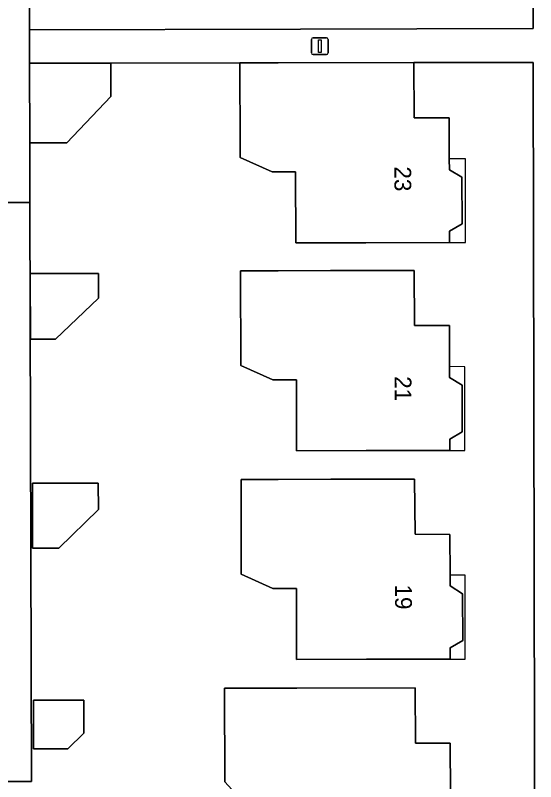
# Model space of a CAD drawing. Extents: x 160455 to 162082, y 388339 to 389736.
# Drawn here: x 160984.32 to 161015.38, y 388503.52 to 388549.23 of the extents above; entities that cross this region are included whole.
import ezdxf

# ---------------------------------------------------------------- set-up
doc = ezdxf.new("R2010")
doc.units = 0
for name, color, linetype in [('IMGEO_Erf', 7, 'Continuous'), ('IMGEO_Lichtmast', 7, 'Continuous'), ('IMGEO_Muur', 7, 'Continuous'), ('IMGEO_Pand', 7, 'Continuous'), ('IMGEO_Pand_nummerreeks', 7, 'Continuous'), ('IMGEO_Pand_overbouw', 7, 'Continuous'), ('IMGEO_Voetpad_open', 7, 'Continuous')]:
    doc.layers.add(name, color=color, linetype=linetype)

msp = doc.modelspace()

# ---------------------------------------------------------------- linework, layer by layer
at = {"layer": 'IMGEO_Erf'}
for points in [[(160985.147, 388555.481), (160985.162, 388548.37), (161001.342, 388548.405), (161015.222, 388548.437), (161015.058, 388617.261)], [(161015.227, 388546.422), (161008.109, 388546.416), (161008.121, 388543.125), (161010.216, 388543.124), (161010.223, 388540.674), (161010.225, 388540.025), (161010.976, 388539.588), (161010.984, 388536.798), (161010.235, 388536.354), (161010.237, 388535.676), (161005.238, 388535.665), (161001.058, 388535.656), (161001.049, 388539.896), (161000, 388539.895), (160999.64, 388539.894), (160997.732, 388540.742), (160997.731, 388541.393), (160997.719, 388546.392), (160990.022, 388546.381), (160990.025, 388544.381), (160987.387, 388541.627), (160985.179, 388541.624), (160985.186, 388538.067), (160985.273, 388503.533), (160983.484, 388503.529)], [(161015.378, 388466.056), (161015.323, 388500), (161015.314, 388505.844), (161015.227, 388546.422)]]:
    msp.add_lwpolyline(points, dxfattribs=at)
for points in [[(160997.764, 388533.994), (161000, 388533.999), (161003.127, 388534.006), (161008.126, 388534.018), (161008.138, 388530.725), (161010.233, 388530.724), (161010.239, 388528.287), (161010.24, 388527.625), (161010.992, 388527.177), (161010.999, 388524.397), (161010.249, 388523.955), (161010.251, 388523.28), (161005.252, 388523.268), (161001.103, 388523.258), (161001.094, 388527.498), (161000, 388527.496), (160999.685, 388527.496), (160997.777, 388528.344)], [(160986.721, 388529.919), (160985.215, 388529.917), (160985.209, 388533.83), (160989.277, 388533.837), (160989.279, 388532.352)], [(161000, 388521.551), (161003.154, 388521.558), (161008.153, 388521.57), (161008.178, 388518.279), (161010.258, 388518.273), (161010.264, 388515.837), (161010.266, 388515.204), (161011.018, 388514.726), (161011.025, 388511.936), (161010.275, 388511.504), (161010.277, 388510.837), (161005.278, 388510.823), (161001.109, 388510.811), (161001.1, 388515.051), (161000, 388515.049), (160999.691, 388515.049), (160997.804, 388515.896), (160997.791, 388521.546)], [(160989.269, 388521.336), (160989.272, 388519.753), (160986.907, 388517.46), (160985.342, 388517.457), (160985.336, 388521.329)], [(161001.116, 388509.103), (161008.174, 388509.116), (161008.197, 388505.827), (161010.281, 388505.821), (161010.286, 388502.822), (161011.038, 388502.364), (161011.042, 388500), (161011.043, 388499.594), (161010.294, 388499.122), (161010.295, 388498.386), (161005.296, 388498.377), (161001.136, 388498.369), (161001.133, 388500), (161001.128, 388502.6), (160999.709, 388502.598), (160997.654, 388502.606), (160996.823, 388503.51), (160996.81, 388509.093), (160997.809, 388509.095)], [(160988.405, 388508.394), (160988.409, 388506.417), (160987.454, 388505.485), (160985.408, 388505.481), (160985.402, 388508.387)]]:
    msp.add_lwpolyline(points, close=True, dxfattribs=at)
at = {"layer": 'IMGEO_Lichtmast'}
for p, q in [((161001.995, 388546.99), (161001.995, 388547.79)), ((161001.995, 388547.79), (161001.995, 388546.99)), ((161002.095, 388547.89), (161002.885, 388547.89)), ((161002.885, 388547.89), (161002.095, 388547.89)), ((161002.985, 388547.79), (161002.985, 388546.99)), ((161002.985, 388546.99), (161002.985, 388547.79)), ((161002.885, 388546.89), (161002.095, 388546.89)), ((161002.095, 388546.89), (161002.885, 388546.89))]:
    msp.add_line(p, q, dxfattribs=at)
msp.add_lwpolyline([(161002.415, 388547.765), (161002.565, 388547.765), (161002.565, 388547.015), (161002.415, 388547.015), (161002.415, 388547.765)], dxfattribs=at)
for centre, start, end in [((161002.095, 388547.79), 90, 180), ((161002.095, 388547.79), 90, 180), ((161002.885, 388547.79), 0, 90), ((161002.885, 388547.79), 360, 90), ((161002.095, 388546.99), 180, 270), ((161002.095, 388546.99), 180, 270), ((161002.885, 388546.99), 270, 0), ((161002.885, 388546.99), 270, 0)]:
    msp.add_arc(centre, 0.1, start, end, dxfattribs=at)
at = {"layer": 'IMGEO_Muur'}
for points in [[(160985.147, 388555.481), (160985.162, 388548.37), (161001.342, 388548.405)], [(160997.719, 388546.392), (160989.252, 388546.38)], [(160985.186, 388538.067), (160985.178, 388542.195)]]:
    msp.add_lwpolyline(points, dxfattribs=at)
at = {"layer": 'IMGEO_Pand'}
for points in [[(160990.022, 388546.381), (160985.172, 388546.374), (160985.179, 388541.624), (160987.387, 388541.627), (160990.025, 388544.381)], [(160997.719, 388546.392), (160997.731, 388541.393), (160997.732, 388540.742), (160999.64, 388539.894), (161000, 388539.895), (161001.049, 388539.896), (161001.058, 388535.656), (161005.238, 388535.665), (161010.237, 388535.676), (161010.235, 388536.354), (161010.984, 388536.798), (161010.976, 388539.588), (161010.225, 388540.025), (161010.223, 388540.674), (161010.216, 388543.124), (161008.121, 388543.125), (161008.109, 388546.416), (161000, 388546.397)], [(161003.127, 388534.006), (161000, 388533.999), (160997.764, 388533.994), (160997.777, 388528.344), (160999.685, 388527.496), (161000, 388527.496), (161001.094, 388527.498), (161001.103, 388523.258), (161005.252, 388523.268), (161010.251, 388523.28), (161010.249, 388523.955), (161010.999, 388524.397), (161010.992, 388527.177), (161010.24, 388527.625), (161010.239, 388528.287), (161010.233, 388530.724), (161008.138, 388530.725), (161008.126, 388534.018)], [(160985.209, 388533.83), (160985.215, 388529.917), (160986.721, 388529.919), (160989.279, 388532.352), (160989.277, 388533.837)], [(161005.278, 388510.823), (161010.277, 388510.837), (161010.275, 388511.504), (161011.025, 388511.936), (161011.018, 388514.726), (161010.266, 388515.204), (161010.264, 388515.837), (161010.258, 388518.273), (161008.178, 388518.279), (161008.153, 388521.57), (161003.154, 388521.558), (161000, 388521.551), (160997.791, 388521.546), (160997.804, 388515.896), (160999.691, 388515.049), (161000, 388515.049), (161001.1, 388515.051), (161001.109, 388510.811)], [(160985.342, 388517.457), (160986.907, 388517.46), (160989.272, 388519.753), (160989.269, 388521.336), (160985.336, 388521.329)], [(161005.296, 388498.377), (161010.295, 388498.386), (161010.294, 388499.122), (161011.043, 388499.594), (161011.042, 388500), (161011.038, 388502.364), (161010.286, 388502.822), (161010.281, 388505.821), (161008.197, 388505.827), (161008.174, 388509.116), (161001.116, 388509.103), (160997.809, 388509.095), (160996.81, 388509.093), (160996.823, 388503.51), (160997.654, 388502.606), (160999.709, 388502.598), (161001.128, 388502.6), (161001.133, 388500), (161001.136, 388498.369)], [(160985.402, 388508.387), (160985.408, 388505.481), (160987.454, 388505.485), (160988.409, 388506.417), (160988.405, 388508.394)]]:
    msp.add_lwpolyline(points, close=True, dxfattribs=at)
at = {"layer": 'IMGEO_Pand_overbouw'}
for points in [[(161010.237, 388535.676), (161011.182, 388535.673), (161011.197, 388540.663), (161010.223, 388540.674), (161010.225, 388540.025), (161010.976, 388539.588), (161010.984, 388536.798), (161010.235, 388536.354)], [(161010.239, 388528.287), (161010.24, 388527.625), (161010.992, 388527.177), (161010.999, 388524.397), (161010.249, 388523.955), (161010.251, 388523.28), (161011.148, 388523.282), (161011.144, 388528.265)], [(161010.277, 388510.837), (161011.178, 388510.837), (161011.162, 388515.845), (161010.264, 388515.837), (161010.266, 388515.204), (161011.018, 388514.726), (161011.025, 388511.936), (161010.275, 388511.504)]]:
    msp.add_lwpolyline(points, close=True, dxfattribs=at)
at = {"layer": 'IMGEO_Voetpad_open'}
msp.add_lwpolyline([(161015.058, 388617.261), (161015.222, 388548.437), (161001.342, 388548.405), (160985.162, 388548.37), (160985.172, 388546.374), (160990.022, 388546.381), (160997.719, 388546.392), (161000, 388546.397), (161008.109, 388546.416), (161015.227, 388546.422), (161015.314, 388505.844), (161015.323, 388500), (161015.378, 388466.056)], dxfattribs=at)
for points in [[(160985.147, 388555.481), (160983.369, 388555.475), (160968.14, 388555.428), (160958.051, 388555.395), (160958.068, 388552.684), (160982.455, 388552.733), (160982.501, 388540.818), (160958.098, 388540.667), (160958.111, 388537.937), (160968.208, 388537.986), (160983.437, 388538.059), (160985.186, 388538.067), (160985.179, 388541.624), (160985.172, 388546.374), (160985.162, 388548.37)], [(160985.186, 388538.067), (160983.437, 388538.059), (160983.443, 388533.649), (160983.447, 388530.55), (160983.452, 388527.449), (160983.458, 388522.858), (160983.463, 388519.74), (160983.467, 388516.658), (160983.47, 388514.368), (160983.475, 388512.05), (160983.48, 388508.936), (160983.484, 388505.85), (160983.484, 388503.529), (160985.273, 388503.533)]]:
    msp.add_lwpolyline(points, close=True, dxfattribs=at)

# ---------------------------------------------------------------- texts
at = {"layer": 'IMGEO_Pand_nummerreeks'}
for s, rotation, p in [('23', 270.1615, (161006.945, 388540.217)), ('21', 270.1385, (161006.96, 388527.707)), ('19', 270.1464, (161006.986, 388515.282))]:
    msp.add_text(s, height=1, rotation=rotation, dxfattribs=at).set_placement(p)

doc.saveas('drawing.dxf')
